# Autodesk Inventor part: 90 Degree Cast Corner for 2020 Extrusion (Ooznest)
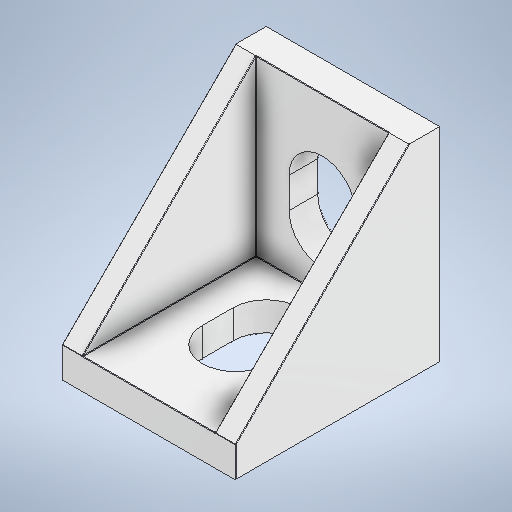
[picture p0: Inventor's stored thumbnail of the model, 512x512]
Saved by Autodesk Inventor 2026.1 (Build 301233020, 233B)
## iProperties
Created: 2021-06
Part Number: 90 Degree Cast Corner for 2020 Extrusion (Ooznest)
Material: Steel
Document SubType Name: Modeling
Designer: hp
Density: 7.85 g/cm^3
Appearance: Default
Title: C:/Users/PC One/OriginDesigned Dropbox/Dropbox OriginDesigned/001 Origin/007 Origin Tech/.KANE MODELS/Ooznest 90 Degree Cast Corner for 2020 Extrusion/Design/Ooznest 90 Degree Cast Corner for 2020 Ext
Sending System: Autodesk Translation Framework v10.9.0.1377
Preprocessor: ST-DEVELOPER v18.1
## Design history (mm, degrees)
feature "Body1"
body "Solid1"
